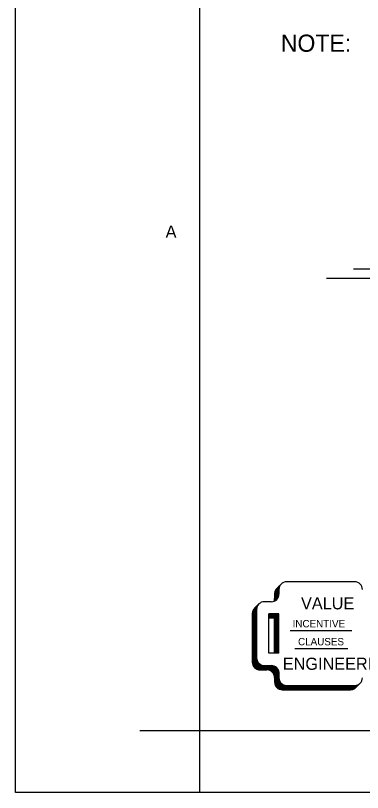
# Model space of a CAD drawing. Extents: x 22369.62 to 22373.29, y 22369.62 to 22372.46.
# Drawn here: x 22369.621 to 22369.857, y 22369.621 to 22370.149 of the extents above; entities that cross this region are included whole.
import ezdxf

# ---------------------------------------------------------------- set-up
doc = ezdxf.new("R2010")
doc.units = 0
for name, color, linetype in [('Level 1', 7, 'Continuous'), ('Level 10', 7, 'Continuous'), ('Level 2', 7, 'Continuous'), ('Level 4', 7, 'Continuous'), ('Level 7', 7, 'Continuous'), ('Level 9', 7, 'Continuous')]:
    doc.layers.add(name, color=color, linetype=linetype)

msp = doc.modelspace()

# ---------------------------------------------------------------- linework, layer by layer
at = {"layer": 'Level 1'}
msp.add_lwpolyline([(22369.6213, 22372.4553), (22373.288, 22372.4553), (22373.288, 22369.6213), (22369.6213, 22369.6213)], close=True, dxfattribs=at)
at = {"layer": 'Level 10'}
for p, q in [((22369.8508, 22369.97679), (22370.20301, 22369.97679)), ((22369.83234, 22369.97038), (22370.23488, 22369.97038)), ((22369.7056, 22369.6633), (22369.74615, 22369.6633)), ((22369.7463, 22369.6213), (22369.7463, 22369.6633))]:
    msp.add_line(p, q, dxfattribs=at)
at = {"layer": 'Level 2'}
for p, q in [((22369.79866, 22369.7598), (22369.80161, 22369.76275)), ((22369.80034, 22369.76065), (22369.80034, 22369.76148)), ((22369.80061, 22369.76133), (22369.80061, 22369.76175)), ((22369.80087, 22369.7618), (22369.80087, 22369.76201)), ((22369.80109, 22369.76213), (22369.80109, 22369.76223)), ((22369.79714, 22369.75611), (22369.79714, 22369.7513)), ((22369.79742, 22369.7578), (22369.79742, 22369.75144)), ((22369.79778, 22369.7586), (22369.79778, 22369.75165)), ((22369.7981, 22369.75912), (22369.7981, 22369.75189)), ((22369.79846, 22369.75957), (22369.79846, 22369.75219)), ((22369.7988, 22369.75993), (22369.7988, 22369.75255)), ((22369.79915, 22369.76029), (22369.79915, 22369.75301)), ((22369.79953, 22369.76066), (22369.79953, 22369.75363)), ((22369.79988, 22369.76102), (22369.79988, 22369.75453)), ((22369.80009, 22369.75906), (22369.80009, 22369.76123)), ((22369.78296, 22369.7456), (22369.78296, 22369.70673)), ((22369.78313, 22369.74584), (22369.78313, 22369.70649)), ((22369.78328, 22369.74602), (22369.78328, 22369.70631)), ((22369.78341, 22369.74617), (22369.78341, 22369.70615)), ((22369.78354, 22369.74631), (22369.78649, 22369.74926)), ((22369.78356, 22369.74632), (22369.78356, 22369.70601)), ((22369.78374, 22369.74651), (22369.78374, 22369.70584)), ((22369.78386, 22369.74663), (22369.78386, 22369.70573)), ((22369.784, 22369.74677), (22369.784, 22369.70562)), ((22369.78416, 22369.74693), (22369.78416, 22369.7055)), ((22369.78434, 22369.74711), (22369.78434, 22369.70537)), ((22369.78449, 22369.74726), (22369.78449, 22369.70528)), ((22369.78462, 22369.74739), (22369.78462, 22369.70519)), ((22369.78476, 22369.74753), (22369.78476, 22369.70512)), ((22369.78485, 22369.74762), (22369.78485, 22369.70507)), ((22369.78497, 22369.74557), (22369.78497, 22369.74774)), ((22369.78508, 22369.74665), (22369.78508, 22369.74785)), ((22369.78523, 22369.74719), (22369.78523, 22369.748)), ((22369.78534, 22369.74751), (22369.78534, 22369.74811)), ((22369.78545, 22369.74775), (22369.78545, 22369.74821)), ((22369.78554, 22369.74794), (22369.78554, 22369.74831)), ((22369.78564, 22369.74814), (22369.78564, 22369.74841)), ((22369.78575, 22369.74831), (22369.78575, 22369.74852)), ((22369.78585, 22369.74848), (22369.78585, 22369.74862)), ((22369.78596, 22369.74862), (22369.78596, 22369.74873)), ((22369.78202, 22369.74262), (22369.78202, 22369.7097)), ((22369.78216, 22369.74384), (22369.78216, 22369.70849)), ((22369.78232, 22369.74437), (22369.78232, 22369.70795)), ((22369.78249, 22369.74478), (22369.78249, 22369.70755)), ((22369.78262, 22369.74506), (22369.78262, 22369.70727)), ((22369.78279, 22369.74535), (22369.78279, 22369.70698)), ((22369.80009, 22369.74231), (22369.7932, 22369.74231)), ((22369.80009, 22369.74217), (22369.7932, 22369.74217)), ((22369.80009, 22369.74202), (22369.7932, 22369.74202)), ((22369.80009, 22369.74186), (22369.7932, 22369.74186)), ((22369.80009, 22369.74169), (22369.7932, 22369.74169)), ((22369.80009, 22369.74154), (22369.7932, 22369.74154)), ((22369.80009, 22369.74138), (22369.7932, 22369.74138)), ((22369.80009, 22369.74121), (22369.7932, 22369.74121)), ((22369.80009, 22369.74107), (22369.7932, 22369.74107)), ((22369.80009, 22369.74091), (22369.7932, 22369.74091)), ((22369.80009, 22369.74076), (22369.7932, 22369.74076)), ((22369.80009, 22369.74061), (22369.7932, 22369.74061)), ((22369.80009, 22369.74046), (22369.7932, 22369.74046)), ((22369.80009, 22369.74034), (22369.7932, 22369.74034)), ((22369.80009, 22369.74244), (22369.79714, 22369.7395)), ((22369.80009, 22369.74018), (22369.7932, 22369.74018)), ((22369.80009, 22369.74006), (22369.7932, 22369.74006)), ((22369.80009, 22369.73992), (22369.7932, 22369.73992)), ((22369.80009, 22369.7398), (22369.7932, 22369.7398)), ((22369.80009, 22369.73964), (22369.7932, 22369.73964)), ((22369.79714, 22369.7395), (22369.7932, 22369.7395)), ((22369.79714, 22369.71578), (22369.79714, 22369.7395)), ((22369.79729, 22369.71578), (22369.79729, 22369.73964)), ((22369.7974, 22369.71578), (22369.7974, 22369.73964)), ((22369.79753, 22369.71578), (22369.79753, 22369.73964)), ((22369.79763, 22369.71578), (22369.79763, 22369.73964)), ((22369.79779, 22369.71578), (22369.79779, 22369.73964)), ((22369.79792, 22369.71578), (22369.79792, 22369.73964)), ((22369.79807, 22369.71578), (22369.79807, 22369.73964)), ((22369.79817, 22369.71578), (22369.79817, 22369.73964)), ((22369.79834, 22369.71578), (22369.79834, 22369.73964)), ((22369.79848, 22369.71578), (22369.79848, 22369.73964)), ((22369.79859, 22369.71578), (22369.79859, 22369.73964)), ((22369.79873, 22369.71578), (22369.79873, 22369.73964)), ((22369.79886, 22369.71578), (22369.79886, 22369.73964)), ((22369.79902, 22369.71578), (22369.79902, 22369.73964)), ((22369.79914, 22369.71578), (22369.79914, 22369.73964)), ((22369.79927, 22369.71578), (22369.79927, 22369.73964)), ((22369.79942, 22369.71578), (22369.79942, 22369.73964)), ((22369.79958, 22369.71578), (22369.79958, 22369.73964)), ((22369.79974, 22369.71578), (22369.79974, 22369.73964)), ((22369.79984, 22369.71578), (22369.79984, 22369.73964)), ((22369.79998, 22369.71578), (22369.79998, 22369.73964)), ((22369.78504, 22369.71179), (22369.78504, 22369.70498)), ((22369.78521, 22369.71109), (22369.78521, 22369.7049)), ((22369.78536, 22369.71066), (22369.78536, 22369.70484)), ((22369.78552, 22369.71032), (22369.78552, 22369.70479)), ((22369.78571, 22369.70998), (22369.78571, 22369.70473)), ((22369.78584, 22369.70977), (22369.78584, 22369.70468)), ((22369.78598, 22369.70957), (22369.78598, 22369.70465)), ((22369.78615, 22369.70934), (22369.78615, 22369.70461)), ((22369.7863, 22369.70917), (22369.7863, 22369.70458)), ((22369.78646, 22369.70901), (22369.78646, 22369.70456)), ((22369.78661, 22369.70885), (22369.78661, 22369.70453)), ((22369.78677, 22369.70871), (22369.78677, 22369.70452)), ((22369.78691, 22369.70859), (22369.78691, 22369.70451)), ((22369.78709, 22369.70845), (22369.78709, 22369.7045)), ((22369.78723, 22369.7045), (22369.79193, 22369.7045)), ((22369.78725, 22369.70834), (22369.78725, 22369.7045)), ((22369.7874, 22369.70825), (22369.7874, 22369.7045)), ((22369.78756, 22369.70815), (22369.78756, 22369.7045)), ((22369.78775, 22369.70805), (22369.78775, 22369.7045)), ((22369.78788, 22369.70798), (22369.78788, 22369.7045)), ((22369.78797, 22369.70793), (22369.78797, 22369.7045)), ((22369.7881, 22369.70787), (22369.7881, 22369.7045)), ((22369.78824, 22369.70782), (22369.78824, 22369.7045)), ((22369.7884, 22369.70776), (22369.7884, 22369.7045)), ((22369.78857, 22369.70769), (22369.78857, 22369.7045)), ((22369.78873, 22369.70765), (22369.78873, 22369.7045)), ((22369.78893, 22369.70759), (22369.78893, 22369.7045)), ((22369.78912, 22369.70755), (22369.78912, 22369.7045)), ((22369.78928, 22369.70752), (22369.78928, 22369.7045)), ((22369.78939, 22369.70751), (22369.78939, 22369.7045)), ((22369.78955, 22369.70749), (22369.78955, 22369.7045)), ((22369.78968, 22369.70746), (22369.78968, 22369.7045)), ((22369.7898, 22369.70745), (22369.7898, 22369.7045)), ((22369.78995, 22369.70744), (22369.78995, 22369.7045)), ((22369.79011, 22369.70744), (22369.79011, 22369.7045)), ((22369.79027, 22369.70744), (22369.79027, 22369.7045)), ((22369.79045, 22369.70744), (22369.79045, 22369.7045)), ((22369.79062, 22369.70744), (22369.79062, 22369.7045)), ((22369.79078, 22369.70744), (22369.79078, 22369.7045)), ((22369.79099, 22369.70744), (22369.79099, 22369.7045)), ((22369.79116, 22369.70744), (22369.79116, 22369.7045)), ((22369.79132, 22369.70744), (22369.79132, 22369.7045)), ((22369.7915, 22369.70744), (22369.7915, 22369.7045)), ((22369.7917, 22369.70744), (22369.7917, 22369.7045)), ((22369.79188, 22369.70744), (22369.79188, 22369.7045)), ((22369.79208, 22369.70744), (22369.79208, 22369.7045)), ((22369.79228, 22369.70744), (22369.79228, 22369.7045)), ((22369.79251, 22369.70744), (22369.79251, 22369.70446)), ((22369.79266, 22369.70744), (22369.79266, 22369.70444)), ((22369.7928, 22369.70744), (22369.7928, 22369.70442)), ((22369.79293, 22369.70744), (22369.79293, 22369.7044)), ((22369.79315, 22369.70744), (22369.79315, 22369.70435)), ((22369.79338, 22369.70744), (22369.79338, 22369.70429)), ((22369.79362, 22369.70744), (22369.79362, 22369.70421)), ((22369.79385, 22369.70744), (22369.79385, 22369.70413)), ((22369.79405, 22369.70744), (22369.79405, 22369.70405)), ((22369.79428, 22369.70744), (22369.79428, 22369.70394)), ((22369.79446, 22369.70744), (22369.79446, 22369.70385)), ((22369.79473, 22369.70744), (22369.79473, 22369.70368)), ((22369.79495, 22369.70744), (22369.79495, 22369.70354)), ((22369.79506, 22369.70744), (22369.79506, 22369.70345)), ((22369.79526, 22369.70744), (22369.79526, 22369.7033)), ((22369.79541, 22369.70741), (22369.79541, 22369.70316)), ((22369.79558, 22369.70739), (22369.79558, 22369.70301)), ((22369.79574, 22369.70737), (22369.79574, 22369.70285)), ((22369.79585, 22369.70735), (22369.79585, 22369.70273)), ((22369.79603, 22369.70732), (22369.79603, 22369.70251)), ((22369.79621, 22369.70728), (22369.79621, 22369.70227)), ((22369.79639, 22369.70723), (22369.79639, 22369.70198)), ((22369.79657, 22369.70716), (22369.79657, 22369.70166)), ((22369.79673, 22369.70711), (22369.79673, 22369.70133)), ((22369.79689, 22369.70704), (22369.79689, 22369.70088)), ((22369.79707, 22369.70696), (22369.79707, 22369.70015)), ((22369.79721, 22369.7069), (22369.79721, 22369.69541)), ((22369.79737, 22369.70681), (22369.79737, 22369.69468)), ((22369.79754, 22369.70671), (22369.79754, 22369.69423)), ((22369.7977, 22369.70662), (22369.7977, 22369.69388)), ((22369.79785, 22369.70652), (22369.79785, 22369.69359)), ((22369.79801, 22369.7064), (22369.79801, 22369.69334)), ((22369.79818, 22369.70627), (22369.79818, 22369.69309)), ((22369.79832, 22369.70615), (22369.79832, 22369.69291)), ((22369.79848, 22369.70601), (22369.79848, 22369.69274)), ((22369.79861, 22369.70587), (22369.79861, 22369.69259)), ((22369.79878, 22369.70569), (22369.79878, 22369.69242)), ((22369.79893, 22369.70551), (22369.79893, 22369.69229)), ((22369.79911, 22369.70528), (22369.79911, 22369.69213)), ((22369.79928, 22369.70503), (22369.79928, 22369.69201)), ((22369.79941, 22369.70481), (22369.79941, 22369.69191)), ((22369.79954, 22369.70457), (22369.79954, 22369.69183)), ((22369.79964, 22369.70435), (22369.79964, 22369.69177)), ((22369.79978, 22369.70402), (22369.79978, 22369.69168)), ((22369.79989, 22369.70366), (22369.79989, 22369.69162)), ((22369.79714, 22369.69929), (22369.79714, 22369.69621)), ((22369.79999, 22369.70327), (22369.79999, 22369.69157)), ((22369.8001, 22369.69883), (22369.8001, 22369.69152)), ((22369.80025, 22369.69789), (22369.80025, 22369.69145)), ((22369.80038, 22369.69744), (22369.80038, 22369.69139)), ((22369.8005, 22369.69714), (22369.8005, 22369.69135)), ((22369.80062, 22369.69687), (22369.80062, 22369.6913)), ((22369.80073, 22369.69667), (22369.80073, 22369.69127)), ((22369.80087, 22369.69642), (22369.80087, 22369.69123)), ((22369.80101, 22369.69621), (22369.80101, 22369.69118)), ((22369.80115, 22369.69601), (22369.80115, 22369.69114)), ((22369.80126, 22369.69588), (22369.80126, 22369.69112)), ((22369.8014, 22369.6957), (22369.8014, 22369.69109)), ((22369.80149, 22369.69561), (22369.80149, 22369.69108)), ((22369.8016, 22369.6955), (22369.8016, 22369.69106)), ((22369.80173, 22369.69537), (22369.80173, 22369.69105)), ((22369.80182, 22369.69529), (22369.80182, 22369.69104)), ((22369.80188, 22369.69524), (22369.80188, 22369.69103)), ((22369.80196, 22369.69517), (22369.80196, 22369.69102)), ((22369.80207, 22369.69508), (22369.80207, 22369.69102)), ((22369.80222, 22369.69496), (22369.80222, 22369.69102)), ((22369.80238, 22369.69485), (22369.80238, 22369.69102)), ((22369.80253, 22369.69476), (22369.80253, 22369.69102)), ((22369.8027, 22369.69465), (22369.8027, 22369.69102)), ((22369.80285, 22369.69457), (22369.80285, 22369.69102)), ((22369.80301, 22369.69449), (22369.80301, 22369.69102)), ((22369.80313, 22369.69442), (22369.80313, 22369.69102)), ((22369.80328, 22369.69436), (22369.80328, 22369.69102)), ((22369.80345, 22369.6943), (22369.80345, 22369.69102)), ((22369.80361, 22369.69424), (22369.80361, 22369.69102)), ((22369.80378, 22369.69418), (22369.80378, 22369.69102)), ((22369.80396, 22369.69413), (22369.80396, 22369.69102)), ((22369.80414, 22369.69408), (22369.80414, 22369.69102)), ((22369.80429, 22369.69405), (22369.80429, 22369.69102)), ((22369.80448, 22369.69402), (22369.80448, 22369.69102)), ((22369.80464, 22369.694), (22369.80464, 22369.69102)), ((22369.80481, 22369.69398), (22369.80481, 22369.69102)), ((22369.80501, 22369.69396), (22369.80501, 22369.69102)), ((22369.80517, 22369.69395), (22369.80517, 22369.69102)), ((22369.80517, 22369.69388), (22369.84864, 22369.69388)), ((22369.80517, 22369.69383), (22369.84864, 22369.69383)), ((22369.80517, 22369.69378), (22369.84864, 22369.69378)), ((22369.80517, 22369.6937), (22369.84864, 22369.6937)), ((22369.80517, 22369.69362), (22369.84864, 22369.69362)), ((22369.80517, 22369.69353), (22369.84864, 22369.69353)), ((22369.80517, 22369.69343), (22369.84864, 22369.69343)), ((22369.80517, 22369.69335), (22369.84864, 22369.69335)), ((22369.80517, 22369.69326), (22369.84864, 22369.69326)), ((22369.80517, 22369.69316), (22369.84864, 22369.69316)), ((22369.80517, 22369.69307), (22369.84864, 22369.69307)), ((22369.80517, 22369.69298), (22369.84864, 22369.69298)), ((22369.80517, 22369.69288), (22369.84864, 22369.69288)), ((22369.80517, 22369.6928), (22369.84864, 22369.6928)), ((22369.84864, 22369.69101), (22369.84864, 22369.69395)), ((22369.84876, 22369.69101), (22369.84876, 22369.69395)), ((22369.84884, 22369.69101), (22369.84884, 22369.69395)), ((22369.84892, 22369.69102), (22369.84892, 22369.69395)), ((22369.84906, 22369.69103), (22369.84906, 22369.69395)), ((22369.84916, 22369.69104), (22369.84916, 22369.69395)), ((22369.84929, 22369.69105), (22369.84929, 22369.69395)), ((22369.84939, 22369.69106), (22369.84939, 22369.69395)), ((22369.84951, 22369.69108), (22369.84951, 22369.69395)), ((22369.8496, 22369.6911), (22369.8496, 22369.69395)), ((22369.84973, 22369.69112), (22369.84973, 22369.69395)), ((22369.84984, 22369.69114), (22369.84984, 22369.69395)), ((22369.84996, 22369.69117), (22369.84996, 22369.69395)), ((22369.8501, 22369.69121), (22369.8501, 22369.69395)), ((22369.85026, 22369.69127), (22369.85026, 22369.69395)), ((22369.85038, 22369.69131), (22369.85038, 22369.69395)), ((22369.85051, 22369.69135), (22369.85051, 22369.69395)), ((22369.85064, 22369.6914), (22369.85064, 22369.69395)), ((22369.85078, 22369.69146), (22369.85078, 22369.69395)), ((22369.85089, 22369.69152), (22369.85089, 22369.69395)), ((22369.85105, 22369.6916), (22369.85105, 22369.69395)), ((22369.85121, 22369.69168), (22369.85121, 22369.69395)), ((22369.85135, 22369.69177), (22369.85135, 22369.69395)), ((22369.8515, 22369.69186), (22369.8515, 22369.69395)), ((22369.85164, 22369.69195), (22369.85164, 22369.69395)), ((22369.85178, 22369.69206), (22369.85178, 22369.69395)), ((22369.85192, 22369.69217), (22369.85192, 22369.69395)), ((22369.85208, 22369.6923), (22369.85208, 22369.69398)), ((22369.85223, 22369.69243), (22369.85223, 22369.694)), ((22369.85233, 22369.69253), (22369.85528, 22369.69548)), ((22369.85235, 22369.69255), (22369.85235, 22369.69401)), ((22369.85249, 22369.69268), (22369.85249, 22369.69403)), ((22369.85259, 22369.69279), (22369.85259, 22369.69405)), ((22369.85272, 22369.69291), (22369.85272, 22369.69408)), ((22369.85282, 22369.69302), (22369.85282, 22369.6941)), ((22369.85293, 22369.69313), (22369.85293, 22369.69413)), ((22369.85306, 22369.69326), (22369.85306, 22369.69416)), ((22369.85314, 22369.69334), (22369.85314, 22369.69419)), ((22369.85325, 22369.69344), (22369.85325, 22369.69423)), ((22369.85334, 22369.69354), (22369.85334, 22369.69426)), ((22369.85345, 22369.69364), (22369.85345, 22369.6943)), ((22369.85351, 22369.6937), (22369.85351, 22369.69432)), ((22369.85363, 22369.69383), (22369.85363, 22369.69437)), ((22369.85373, 22369.69392), (22369.85373, 22369.69441)), ((22369.85383, 22369.69403), (22369.85383, 22369.69446)), ((22369.85395, 22369.69414), (22369.85395, 22369.69452)), ((22369.85404, 22369.69424), (22369.85404, 22369.69457)), ((22369.85413, 22369.69433), (22369.85413, 22369.69462)), ((22369.85423, 22369.69442), (22369.85423, 22369.69467)), ((22369.85433, 22369.69453), (22369.85433, 22369.69474)), ((22369.85443, 22369.69463), (22369.85443, 22369.6948)), ((22369.85453, 22369.69473), (22369.85453, 22369.69486)), ((22369.85462, 22369.69482), (22369.85462, 22369.69492)), ((22369.85472, 22369.69491), (22369.85472, 22369.695)), ((22369.80235, 22369.69101), (22369.84864, 22369.69101)), ((22369.80517, 22369.6927), (22369.84864, 22369.6927)), ((22369.80517, 22369.69262), (22369.84864, 22369.69262)), ((22369.80517, 22369.69254), (22369.84864, 22369.69254)), ((22369.80517, 22369.69244), (22369.84864, 22369.69244)), ((22369.80517, 22369.69235), (22369.84864, 22369.69235)), ((22369.80517, 22369.69225), (22369.84864, 22369.69225)), ((22369.80517, 22369.69214), (22369.84864, 22369.69214)), ((22369.80517, 22369.69204), (22369.84864, 22369.69204)), ((22369.80517, 22369.69194), (22369.84864, 22369.69194)), ((22369.80517, 22369.69183), (22369.84864, 22369.69183)), ((22369.80517, 22369.69173), (22369.84864, 22369.69173)), ((22369.80517, 22369.69161), (22369.84864, 22369.69161)), ((22369.80517, 22369.6915), (22369.84864, 22369.6915)), ((22369.80517, 22369.69137), (22369.84864, 22369.69137)), ((22369.80517, 22369.69126), (22369.84864, 22369.69126)), ((22369.80517, 22369.69114), (22369.84864, 22369.69114))]:
    msp.add_line(p, q, dxfattribs=at)
for centre, start, end in [((22369.80234, 22369.75611), 111.4079, 180), ((22369.79193, 22369.75304), 338.5921, 0), ((22369.78722, 22369.74262), 111.4079, 180), ((22369.78722, 22369.70971), 180, 270), ((22369.79193, 22369.69929), 0, 90), ((22369.80234, 22369.69622), 180, 270), ((22369.84864, 22369.69622), 270, 338.5921)]:
    msp.add_arc(centre, 0.00521, start, end, dxfattribs=at)
at = {"layer": 'Level 7'}
for p, q in [((22369.85159, 22369.76427), (22369.8053, 22369.76427)), ((22369.80009, 22369.75906), (22369.80009, 22369.75599)), ((22369.79488, 22369.75078), (22369.79017, 22369.75078)), ((22369.78497, 22369.74557), (22369.78497, 22369.71265)), ((22369.80009, 22369.74244), (22369.7932, 22369.74244)), ((22369.7932, 22369.71578), (22369.7932, 22369.74244)), ((22369.80009, 22369.71578), (22369.80009, 22369.74244)), ((22369.80764, 22369.73112), (22369.84947, 22369.73112)), ((22369.81079, 22369.71912), (22369.84688, 22369.71912)), ((22369.80009, 22369.71578), (22369.7932, 22369.71578)), ((22369.79017, 22369.70744), (22369.79488, 22369.70744)), ((22369.80009, 22369.70224), (22369.80009, 22369.69916)), ((22369.8053, 22369.69395), (22369.85159, 22369.69395))]:
    msp.add_line(p, q, dxfattribs=at)
for centre, start, end in [((22369.80529, 22369.75906), 90, 180), ((22369.85158, 22369.75906), 0, 90), ((22369.79017, 22369.74557), 90, 180), ((22369.79488, 22369.75599), 270, 0), ((22369.79017, 22369.71265), 180, 270), ((22369.79488, 22369.70224), 0, 90), ((22369.80529, 22369.69916), 180, 270), ((22369.85158, 22369.69916), 270, 0)]:
    msp.add_arc(centre, 0.00521, start, end, dxfattribs=at)
at = {"layer": 'Level 9'}
for q in [(22369.7463, 22372.4133), (22373.017, 22369.6633)]:
    msp.add_line((22369.7463, 22369.6633), q, dxfattribs=at)

# ---------------------------------------------------------------- texts
at = {"layer": 'Level 1'}
msp.add_text('A', height=0.00833, dxfattribs=at).set_placement((22369.72316, 22369.99777))
at = {"layer": 'Level 2'}
for s, height, p in [('VALUE', 0.008249, (22369.81508, 22369.74557)), ('INCENTIVE', 0.005, (22369.80937, 22369.73336)), ('CLAUSES', 0.005, (22369.81304, 22369.72117)), ('ENGINEERING', 0.0082494, (22369.80273, 22369.70454))]:
    msp.add_text(s, height=height, dxfattribs=at).set_placement(p)
at = {"layer": 'Level 4'}
msp.add_text('NOTE:', height=0.011698, dxfattribs=at).set_placement((22369.80137, 22370.12403))

doc.saveas('drawing.dxf')
